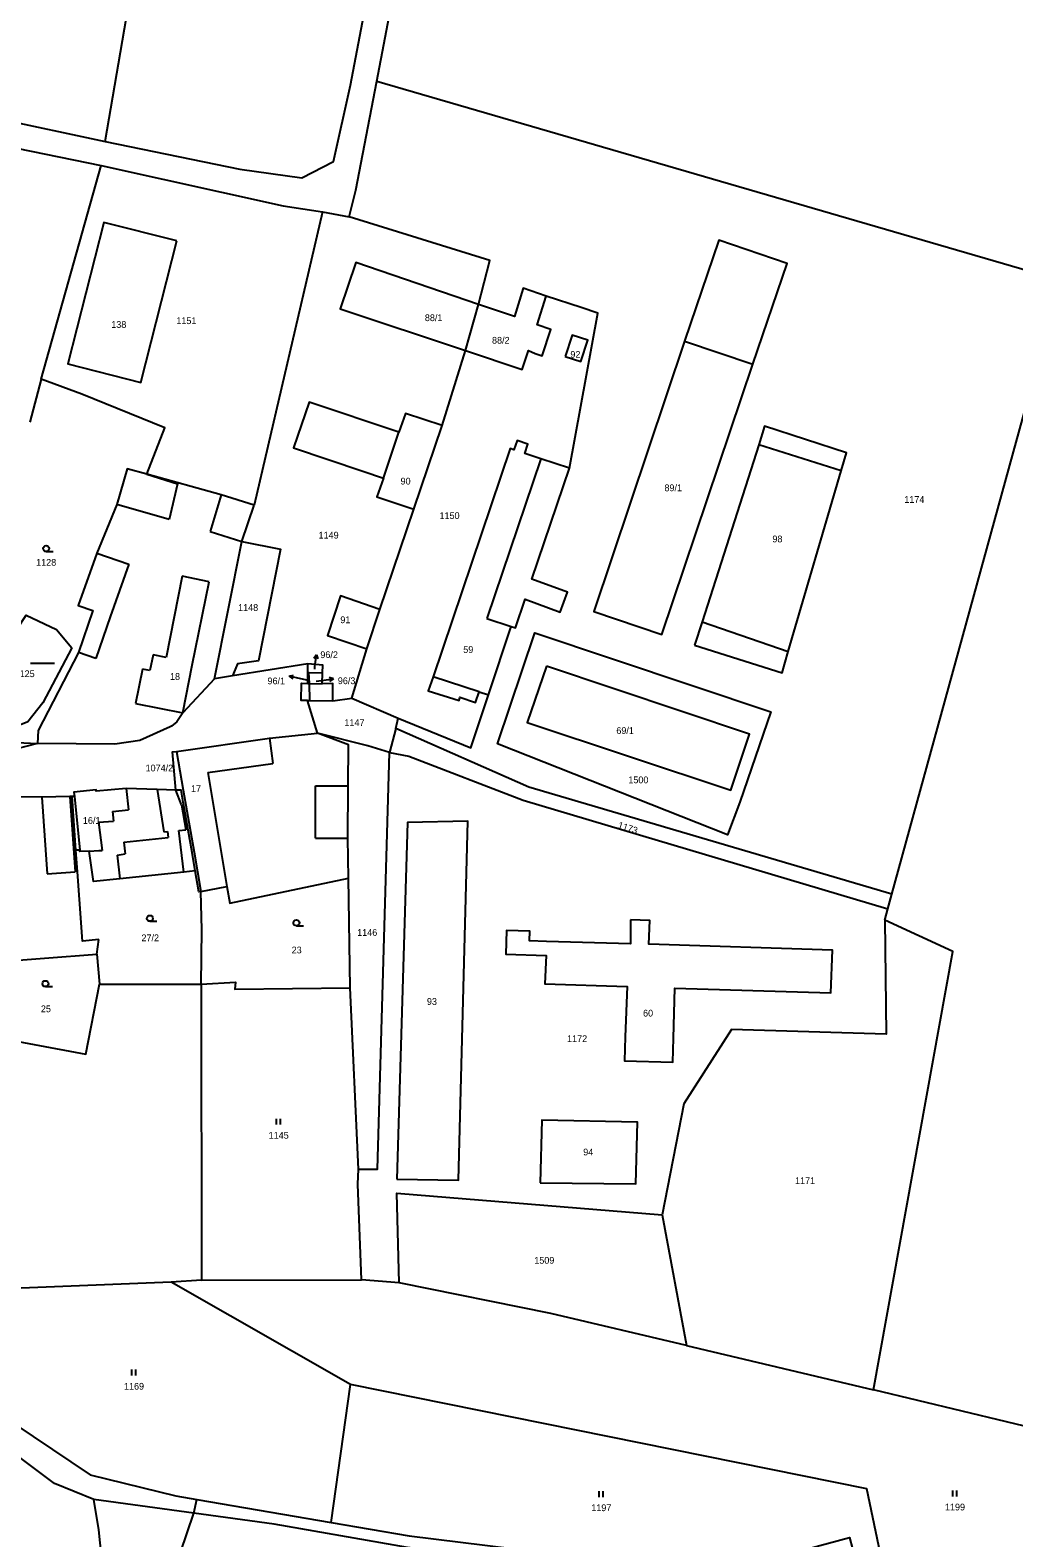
# Model space of a CAD drawing. Extents: x -746176 to -739709, y -1128407 to -1124482.
# Drawn here: x -742113 to -741865.4, y -1126240.2 to -1125860.6 of the extents above; entities that cross this region are included whole.
import ezdxf

# ---------------------------------------------------------------- set-up
doc = ezdxf.new("R2010")
doc.units = 0
for name, color, linetype in [('Hranice parcel', 7, 'Continuous'), ('Parcelní čísla', 7, 'Continuous'), ('Pop  PČ popisy', 7, 'Continuous'), ('Vnitřní kresba', 7, 'Continuous'), ('Značky kultur', 7, 'Continuous')]:
    doc.layers.add(name, color=color, linetype=linetype)

msp = doc.modelspace()

# ---------------------------------------------------------------- linework, layer by layer
at = {"layer": 'Hranice parcel'}
for p, q in [((-742183.95, -1125869.36), (-742094.09, -1125888.65)), ((-742025.73, -1125873.42), (-741853.62, -1125923.53)), ((-742110.2, -1125948.49), (-742095.09, -1125894.63)), ((-742039.44, -1125906.35), (-742056.59, -1125980.21)), ((-742039.44, -1125906.35), (-742032.71, -1125907.6)), ((-741896.07, -1126078.15), (-741853.62, -1125923.53)), ((-742003.37, -1125941.28), (-742000.14, -1125929.62)), ((-742009.27, -1125960.16), (-742003.37, -1125941.28)), ((-742110.2, -1125948.49), (-742113.1, -1125959.31)), ((-742016.41, -1125981.19), (-742009.27, -1125960.16)), ((-742059.7, -1125989.31), (-742056.59, -1125980.21)), ((-742024.98, -1126006.42), (-742016.41, -1125981.19)), ((-742066.57, -1126023.9), (-742059.7, -1125989.31)), ((-742028.28, -1126016.33), (-742024.98, -1126006.42)), ((-742032.05, -1126028.8), (-742028.28, -1126016.33)), ((-742043.09, -1126020.1), (-742062.06, -1126023.17)), ((-742043.1, -1126022.18), (-742043.09, -1126020.1)), ((-742062.06, -1126023.17), (-742066.57, -1126023.9)), ((-742042.81, -1126022.34), (-742043.1, -1126022.18)), ((-742042.81, -1126022.34), (-742039.39, -1126022.39)), ((-742043.15, -1126029.36), (-742042.59, -1126029.36)), ((-742040.7, -1126037.59), (-742043.15, -1126029.36)), ((-742042.59, -1126029.36), (-742036.84, -1126029.41)), ((-742036.84, -1126029.41), (-742032.05, -1126028.8)), ((-742032.05, -1126028.8), (-742020.33, -1126033.81)), ((-742020.91, -1126036.38), (-742020.33, -1126033.81)), ((-742129.13, -1126039.33), (-742111.14, -1126040.16)), ((-742020.91, -1126036.38), (-742022.54, -1126042.43)), ((-742111.14, -1126040.16), (-742129.74, -1126045.05)), ((-742101.5, -1126067.04), (-742102.46, -1126053.55)), ((-742032.44, -1126101.72), (-742032.84, -1126074.12)), ((-741897.09, -1126081.86), (-741896.07, -1126078.15)), ((-741897.86, -1126084.67), (-741897.09, -1126081.86)), ((-742096.2, -1126093.22), (-742095.72, -1126089.56)), ((-742096.2, -1126093.22), (-742095.59, -1126100.8)), ((-742095.59, -1126100.8), (-742069.93, -1126100.8)), ((-742069.93, -1126100.8), (-742069.89, -1126175.3)), ((-742030.37, -1126147.41), (-742032.44, -1126101.72)), ((-741953.9, -1126158.9), (-741947.79, -1126191.81)), ((-742077.47, -1126175.84), (-742168.29, -1126179.42)), ((-742069.89, -1126175.3), (-742077.47, -1126175.84)), ((-742032.39, -1126201.61), (-742077.47, -1126175.84)), ((-742069.89, -1126175.3), (-742029.6, -1126175.24)), ((-742020.09, -1126175.98), (-742029.6, -1126175.24)), ((-741947.79, -1126191.81), (-741900.7, -1126202.92)), ((-742037.23, -1126236.37), (-742032.39, -1126201.61)), ((-742071.8, -1126233.98), (-742097.01, -1126230.58)), ((-742071.8, -1126233.98), (-742071.02, -1126230.56)), ((-742071.02, -1126230.56), (-742037.23, -1126236.37)), ((-742079.26, -1126255.9), (-742071.8, -1126233.98))]:
    msp.add_line(p, q, dxfattribs=at)
for points in [[(-742025.73, -1125873.42), (-742012.38, -1125803.46), (-741995.51, -1125733.06), (-742004.97, -1125730.01), (-742058.67, -1125709.14), (-742078.17, -1125699.67)], [(-742094.09, -1125888.65), (-742080.13, -1125806.83), (-742063.47, -1125714.3)], [(-742094.09, -1125888.65), (-742060.22, -1125895.6), (-742044.65, -1125897.78), (-742036.67, -1125893.62), (-742032.34, -1125874.39), (-742019.34, -1125806.06), (-742005.72, -1125747.44), (-742012.74, -1125735.48), (-742063.47, -1125714.3)], [(-742032.71, -1125907.6), (-742030.98, -1125900.89), (-742025.73, -1125873.42)], [(-742184.93, -1125900.23), (-742180.03, -1125877.3), (-742095.09, -1125894.63)], [(-742095.09, -1125894.63), (-742049.29, -1125904.84), (-742039.44, -1125906.35)], [(-742076.08, -1125913.65), (-742094.46, -1125908.99), (-742103.48, -1125944.63), (-742085.12, -1125949.32), (-742076.08, -1125913.65)], [(-742000.14, -1125929.62), (-741997.3, -1125918.59), (-742032.71, -1125907.6)], [(-741948.24, -1125938.93), (-741971.13, -1126006.96), (-741953.96, -1126012.73), (-741931.04, -1125944.72), (-741922.42, -1125919.3), (-741939.63, -1125913.5), (-741948.24, -1125938.93)], [(-742000.14, -1125929.62), (-742030.99, -1125919.07), (-742034.95, -1125930.75), (-742003.37, -1125941.28)], [(-741983.12, -1125927.57), (-741988.87, -1125925.58), (-741991.1, -1125932.71), (-742000.14, -1125929.62)], [(-742003.37, -1125941.28), (-741989.17, -1125946.02), (-741987.51, -1125941.24), (-741985.88, -1125941.99), (-741984.14, -1125942.59), (-741981.91, -1125935.96), (-741985.33, -1125934.79), (-741983.12, -1125927.57)], [(-741977.26, -1125970.9), (-741970.11, -1125931.84), (-741974.27, -1125930.38), (-741983.12, -1125927.57)], [(-741978.34, -1125942.74), (-741974.4, -1125943.99), (-741972.64, -1125938.6), (-741976.57, -1125937.35), (-741978.34, -1125942.74)], [(-742083.62, -1125972.35), (-742079.06, -1125960.68), (-742100.01, -1125952.25), (-742110.2, -1125948.49)], [(-742009.27, -1125960.16), (-742018.55, -1125957.12), (-742020.18, -1125961.82), (-742042.75, -1125954.21), (-742046.69, -1125965.77), (-742029.22, -1125971.6), (-742024.09, -1125973.38), (-742025.69, -1125978.06), (-742016.41, -1125981.19)], [(-741945.78, -1126015.41), (-741923.72, -1126022.36), (-741922.19, -1126017.01), (-741908.83, -1125971.52), (-741907.48, -1125966.99), (-741928.12, -1125960.33), (-741929.55, -1125965), (-741943.86, -1126009.55), (-741945.78, -1126015.41)], [(-741977.26, -1125970.9), (-741984.48, -1125968.49), (-741988.45, -1125967.15), (-741987.71, -1125964.8), (-741990.43, -1125963.92), (-741991.22, -1125966.22), (-741992.2, -1125965.9), (-742011.53, -1126023.39), (-742012.8, -1126026.9), (-742005.02, -1126029.4), (-742004.82, -1126028.56), (-742000.88, -1126029.89), (-741999.98, -1126027.2), (-741997.64, -1126027.97)], [(-742083.62, -1125972.35), (-742088.6, -1125971), (-742091.15, -1125980.05), (-742096.25, -1125992.27), (-742100.92, -1126005.44), (-742097.24, -1126006.74), (-742100.81, -1126017.24), (-742110.99, -1126036.95), (-742111.14, -1126040.16)], [(-741997.64, -1126027.97), (-741991.88, -1126010.76), (-741990.85, -1126011.08), (-741988.4, -1126003.84), (-741979.54, -1126007.11), (-741977.75, -1126002.07), (-741986.72, -1125998.84), (-741977.26, -1125970.9)], [(-742056.59, -1125980.21), (-742064.93, -1125977.61), (-742083.62, -1125972.35)], [(-742059.7, -1125989.31), (-742049.97, -1125991.24), (-742055.51, -1126019.42), (-742060.79, -1126020.17), (-742062.06, -1126023.17)], [(-742024.98, -1126006.42), (-742034.84, -1126003.05), (-742038.12, -1126013), (-742028.28, -1126016.33)], [(-742102.49, -1126016.08), (-742109.85, -1126029.96), (-742113.56, -1126034.73), (-742116.68, -1126036.01), (-742124.54, -1126036.07), (-742122.99, -1126021.43), (-742114.02, -1126007.91), (-742106.36, -1126011.45), (-742102.49, -1126016.08)], [(-741934.31, -1126054.99), (-741937.49, -1126063.18), (-741995.38, -1126040.29), (-741985.96, -1126012.29), (-741926.53, -1126032.26), (-741934.31, -1126054.99)], [(-742039.39, -1126022.39), (-742039.34, -1126020.44), (-742043.09, -1126020.1)], [(-742066.57, -1126023.9), (-742074.61, -1126032.51), (-742076.07, -1126034.7), (-742077.43, -1126035.79), (-742077.73, -1126036.03), (-742085.38, -1126039.46), (-742091.7, -1126040.33), (-742111.14, -1126040.16)], [(-742043.15, -1126029.36), (-742044.74, -1126029.34), (-742044.72, -1126025.04), (-742043.12, -1126025.05), (-742043.1, -1126022.18)], [(-742042.59, -1126029.36), (-742042.72, -1126025.06), (-742042.81, -1126022.34)], [(-742036.84, -1126029.41), (-742036.81, -1126025.09), (-742039.47, -1126025.15), (-742039.39, -1126022.39)], [(-741982.98, -1126020.68), (-741987.88, -1126034.92), (-741936.6, -1126051.97), (-741931.88, -1126037.81), (-741982.98, -1126020.68)], [(-742020.33, -1126033.81), (-742002.07, -1126041.31), (-741997.64, -1126027.97)], [(-742076.34, -1126051.97), (-742077.13, -1126042.33), (-742076.14, -1126042.19), (-742052.73, -1126038.82), (-742040.7, -1126037.59)], [(-742032.84, -1126074.12), (-742032.99, -1126064.03), (-742032.96, -1126050.85), (-742032.89, -1126040.53), (-742040.7, -1126037.59)], [(-742022.54, -1126042.43), (-742027.96, -1126040.77), (-742040.7, -1126037.59)], [(-741896.07, -1126078.15), (-741987.48, -1126051.17), (-742020.91, -1126036.38)], [(-742030.37, -1126147.41), (-742025.56, -1126147.41), (-742022.54, -1126042.43)], [(-742022.54, -1126042.43), (-742017.7, -1126043.42), (-741988.87, -1126054.5), (-741897.09, -1126081.86)], [(-742102.46, -1126053.55), (-742103.04, -1126053.58), (-742110.1, -1126053.69), (-742122.3, -1126053.64), (-742129.22, -1126053.96)], [(-742076.34, -1126051.97), (-742081.02, -1126051.8), (-742088.8, -1126051.55), (-742096.36, -1126052.18), (-742096.39, -1126051.88), (-742101.98, -1126052.43), (-742101.87, -1126053.53), (-742102.46, -1126053.55)], [(-742071.45, -1126072.26), (-742072.26, -1126067.68), (-742074.48, -1126054.98), (-742075.02, -1126051.93), (-742076.34, -1126051.97)], [(-742020.72, -1126149.85), (-742005.16, -1126150.17), (-742002.84, -1126059.75), (-742018.01, -1126060.08), (-742020.72, -1126149.85)], [(-742100.6, -1126079.47), (-742101.12, -1126072.48), (-742101.5, -1126067.04)], [(-742071.45, -1126072.26), (-742074.35, -1126072.56), (-742090.46, -1126074.26), (-742097.07, -1126074.96), (-742098.18, -1126067.27), (-742100.49, -1126067.36), (-742100.52, -1126067.06), (-742101.5, -1126067.04)], [(-742070.05, -1126077.42), (-742070.53, -1126077.53), (-742071.45, -1126072.26)], [(-742070.05, -1126077.42), (-742063.46, -1126076.21), (-742062.76, -1126080.36), (-742032.84, -1126074.12)], [(-742069.93, -1126100.8), (-742069.78, -1126087.11), (-742070.05, -1126077.42)], [(-742095.72, -1126089.56), (-742099.85, -1126089.96), (-742100.6, -1126079.47)], [(-741961.88, -1126084.6), (-741961.88, -1126090.64), (-741982.99, -1126090.02), (-741987.3, -1126089.89), (-741987.24, -1126087.43), (-741993.1, -1126087.24), (-741993.29, -1126093.21), (-741983.13, -1126093.55), (-741983.41, -1126100.74), (-741962.73, -1126101.39), (-741963.19, -1126114.03), (-741963.35, -1126120.06), (-741951.25, -1126120.44), (-741951.06, -1126114.42), (-741950.69, -1126101.78), (-741911.44, -1126103.01), (-741911.02, -1126092.25), (-741957.22, -1126090.73), (-741957.01, -1126084.78), (-741961.88, -1126084.6)], [(-741897.86, -1126084.67), (-741897.52, -1126113.4), (-741936.41, -1126112.21), (-741948.42, -1126130.92), (-741953.9, -1126158.9)], [(-741900.7, -1126202.92), (-741880.69, -1126092.53), (-741897.86, -1126084.67)], [(-742126.87, -1126104.84), (-742122.04, -1126104.57), (-742122.69, -1126095.25), (-742096.2, -1126093.22)], [(-742126.87, -1126104.84), (-742126.4, -1126113.31), (-742098.98, -1126118.44), (-742095.59, -1126100.8)], [(-742069.93, -1126100.8), (-742061.28, -1126100.31), (-742061.47, -1126102.08), (-742032.44, -1126101.72)], [(-741984.61, -1126150.82), (-741960.5, -1126151.07), (-741960.14, -1126135.57), (-741984.22, -1126135.03), (-741984.61, -1126150.82)], [(-742029.6, -1126175.24), (-742030.53, -1126151.17), (-742030.37, -1126147.41)], [(-742020.09, -1126175.98), (-742020.71, -1126153.4), (-741953.9, -1126158.9)], [(-741947.79, -1126191.81), (-741981.95, -1126183.75), (-742020.09, -1126175.98)], [(-742159.24, -1126187.68), (-742155.35, -1126185.74), (-742097.93, -1126224.3), (-742076.36, -1126229.64), (-742071.02, -1126230.56)], [(-742097.01, -1126230.58), (-742106.9, -1126226.55), (-742144.78, -1126198.17), (-742157.57, -1126188.32), (-742159.24, -1126187.68)], [(-741895.95, -1126258.73), (-741902.39, -1126227.83), (-742032.39, -1126201.61)], [(-741748.2, -1126234.56), (-741750.5, -1126234.41), (-741798.02, -1126225.94), (-741818.62, -1126222.33), (-741833.76, -1126219.08), (-741900.7, -1126202.92)], [(-742091.11, -1126272.55), (-742093.87, -1126256.26), (-742095.72, -1126238.15), (-742097.01, -1126230.58)], [(-741979.16, -1126247.44), (-742018.02, -1126242.67), (-742051.56, -1126236.78), (-742071.8, -1126233.98)], [(-742037.23, -1126236.37), (-742017.58, -1126239.71), (-741978.86, -1126244.46), (-741935.37, -1126247.86), (-741906.75, -1126240.11), (-741905.97, -1126243.01), (-741935.09, -1126250.9), (-741979.16, -1126247.44)]]:
    msp.add_lwpolyline(points, dxfattribs=at)
at = {"layer": 'Pop  PČ popisy'}
for p, q in [((-742040.93, -1126017.84), (-742041.55, -1126018.77)), ((-742041.3, -1126020.82), (-742040.93, -1126017.84)), ((-742040.93, -1126017.84), (-742040.56, -1126018.9)), ((-742047.78, -1126023.26), (-742046.69, -1126022.97)), ((-742044.84, -1126023.88), (-742047.78, -1126023.26)), ((-742047.78, -1126023.26), (-742046.9, -1126023.95)), ((-742042.93, -1126024.29), (-742044.84, -1126023.88)), ((-742041.38, -1126021.45), (-742041.3, -1126020.82)), ((-742040.98, -1126024.47), (-742039.66, -1126024.31)), ((-742039.66, -1126024.31), (-742036.68, -1126023.94)), ((-742036.68, -1126023.94), (-742037.74, -1126023.57)), ((-742036.68, -1126023.94), (-742037.61, -1126024.56))]:
    msp.add_line(p, q, dxfattribs=at)
at = {"layer": 'Vnitřní kresba'}
for p, q in [((-741948.24, -1125938.93), (-741931.04, -1125944.72)), ((-742024.09, -1125973.38), (-742020.18, -1125961.82)), ((-741908.83, -1125971.52), (-741929.55, -1125965)), ((-741984.48, -1125968.49), (-741998.02, -1126008.75)), ((-742083.62, -1125972.35), (-742075.95, -1125974.83)), ((-742075.95, -1125974.83), (-742078.03, -1125983.81)), ((-742064.93, -1125977.61), (-742067.7, -1125986.84)), ((-742078.03, -1125983.81), (-742091.15, -1125980.05)), ((-742067.7, -1125986.84), (-742059.7, -1125989.31)), ((-742096.25, -1125992.27), (-742088.18, -1125995.04)), ((-742088.18, -1125995.04), (-742092.85, -1126008.32)), ((-742074.74, -1125998.02), (-742078.8, -1126018.57)), ((-742067.98, -1125999.48), (-742074.74, -1125998.02)), ((-742072.26, -1126020.48), (-742067.98, -1125999.48)), ((-742092.85, -1126008.32), (-742096.51, -1126018.77)), ((-741998.02, -1126008.75), (-741991.88, -1126010.76)), ((-741943.86, -1126009.55), (-741922.19, -1126017.01)), ((-742096.51, -1126018.77), (-742100.81, -1126017.24)), ((-742082.06, -1126017.91), (-742082.88, -1126021.83)), ((-742078.8, -1126018.57), (-742082.06, -1126017.91)), ((-742074.61, -1126032.51), (-742072.26, -1126020.48)), ((-742084.74, -1126021.46), (-742086.47, -1126030.1)), ((-742082.88, -1126021.83), (-742084.74, -1126021.46)), ((-741999.98, -1126027.2), (-742011.53, -1126023.39)), ((-742043.12, -1126025.05), (-742042.72, -1126025.06)), ((-742042.72, -1126025.06), (-742039.47, -1126025.15)), ((-742086.47, -1126030.1), (-742074.61, -1126032.51)), ((-742052.73, -1126038.82), (-742051.92, -1126045.22)), ((-742076.14, -1126042.19), (-742074.46, -1126051.94)), ((-742068.27, -1126047.46), (-742051.92, -1126045.22)), ((-742068.27, -1126047.46), (-742063.46, -1126076.21)), ((-742041.18, -1126064.01), (-742041.15, -1126050.84)), ((-742041.15, -1126050.84), (-742032.96, -1126050.85)), ((-742110.1, -1126053.69), (-742108.7, -1126073.04)), ((-742103.04, -1126053.58), (-742101.67, -1126072.53)), ((-742101.87, -1126053.53), (-742100.52, -1126067.06)), ((-742088.8, -1126051.55), (-742088.26, -1126056.93)), ((-742081.02, -1126051.8), (-742079.39, -1126062.46)), ((-742074.88, -1126055.67), (-742076.34, -1126051.97)), ((-742074.46, -1126051.94), (-742071.75, -1126067.57)), ((-742092.24, -1126057.34), (-742088.26, -1126056.93)), ((-742092.24, -1126057.34), (-742092, -1126059.73)), ((-742074.88, -1126055.67), (-742073.82, -1126061.97)), ((-742095.84, -1126060.02), (-742092, -1126059.73)), ((-742095.84, -1126060.02), (-742094.89, -1126067.13)), ((-742075.61, -1126062.13), (-742073.82, -1126061.97)), ((-742074.35, -1126072.56), (-742075.61, -1126062.13)), ((-742089.43, -1126065.01), (-742078.24, -1126063.86)), ((-742089.43, -1126065.01), (-742089.19, -1126067.31)), ((-742079.39, -1126062.46), (-742078.39, -1126062.37)), ((-742078.39, -1126062.37), (-742078.24, -1126063.86)), ((-742041.18, -1126064.01), (-742032.99, -1126064.03)), ((-742098.18, -1126067.27), (-742095.71, -1126067.17)), ((-742095.71, -1126067.17), (-742094.89, -1126067.13)), ((-742091.09, -1126068.35), (-742089.12, -1126068.01)), ((-742091.09, -1126068.35), (-742090.46, -1126074.26)), ((-742089.19, -1126067.31), (-742089.12, -1126068.01)), ((-742071.75, -1126067.57), (-742070.05, -1126077.42)), ((-742108.7, -1126073.04), (-742101.67, -1126072.53))]:
    msp.add_line(p, q, dxfattribs=at)
at = {"layer": 'Značky kultur'}
for p, q in [((-742108.98, -1125991.88), (-742107.23, -1125991.88)), ((-742112.91, -1126019.93), (-742106.91, -1126019.93)), ((-742082.86, -1126084.97), (-742081.11, -1126084.97)), ((-742045.98, -1126086.12), (-742044.23, -1126086.12)), ((-742109.16, -1126101.42), (-742107.41, -1126101.42)), ((-742050.97, -1126136.16), (-742050.97, -1126134.66)), ((-742049.97, -1126136.16), (-742049.97, -1126134.66)), ((-742087.39, -1126199.34), (-742087.39, -1126197.84)), ((-742086.39, -1126199.34), (-742086.39, -1126197.84)), ((-741969.75, -1126229.93), (-741969.75, -1126228.43)), ((-741968.75, -1126229.93), (-741968.75, -1126228.43)), ((-741880.71, -1126229.75), (-741880.71, -1126228.25)), ((-741879.71, -1126229.75), (-741879.71, -1126228.25))]:
    msp.add_line(p, q, dxfattribs=at)
for centre in [(-742108.98, -1125991.13), (-742082.86, -1126084.22), (-742045.98, -1126085.37), (-742109.16, -1126100.67)]:
    msp.add_circle(centre, 0.75, dxfattribs=at)

# ---------------------------------------------------------------- texts
at = {"layer": 'Parcelní čísla'}
for s, p in [('1151', (-742076.21, -1125934.59)), ('88/1', (-742013.64, -1125933.84)), ('138', (-742092.59, -1125935.54)), ('88/2', (-741996.73, -1125939.52)), ('92', (-741977.01, -1125943.07)), ('90', (-742019.75, -1125974.99)), ('89/1', (-741953.33, -1125976.67)), ('1174', (-741892.95, -1125979.61)), ('1150', (-742009.95, -1125983.67)), ('1149', (-742040.4, -1125988.59)), ('98', (-741926.15, -1125989.54)), ('1128', (-742111.5, -1125995.43)), ('1148', (-742060.66, -1126006.81)), ('91', (-742034.92, -1126009.9)), ('59', (-742003.98, -1126017.39)), ('96/2', (-742039.95, -1126018.69)), ('1125', (-742116.93, -1126023.48)), ('18', (-742077.8, -1126024.17)), ('96/1', (-742053.25, -1126025.29)), ('96/3', (-742035.55, -1126025.25)), ('1147', (-742033.9, -1126035.79)), ('69/1', (-741965.44, -1126037.78)), ('1074/2', (-742083.95, -1126047.22)), ('17', (-742072.52, -1126052.4)), ('1500', (-741962.42, -1126050.2)), ('16/1', (-742099.73, -1126060.43)), ('27/2', (-742084.99, -1126089.98)), ('1146', (-742030.68, -1126088.63)), ('23', (-742047.17, -1126093.04)), ('25', (-742110.31, -1126107.85)), ('93', (-742013.12, -1126106.01)), ('60', (-741958.71, -1126108.94)), ('1172', (-741977.84, -1126115.36)), ('1145', (-742052.97, -1126139.71)), ('94', (-741973.77, -1126143.9)), ('1171', (-741920.45, -1126151.12)), ('1509', (-741986.1, -1126171.18)), ('1169', (-742089.39, -1126202.89)), ('1197', (-741971.75, -1126233.48)), ('1199', (-741882.71, -1126233.3))]:
    msp.add_text(s, height=1.7, dxfattribs=at).set_placement(p)
msp.add_text('1173', height=1.7, rotation=342, dxfattribs=at).set_placement((-741965.2, -1126061.45))

doc.saveas('drawing.dxf')
